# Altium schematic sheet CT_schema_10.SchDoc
size 147 x 119 mm
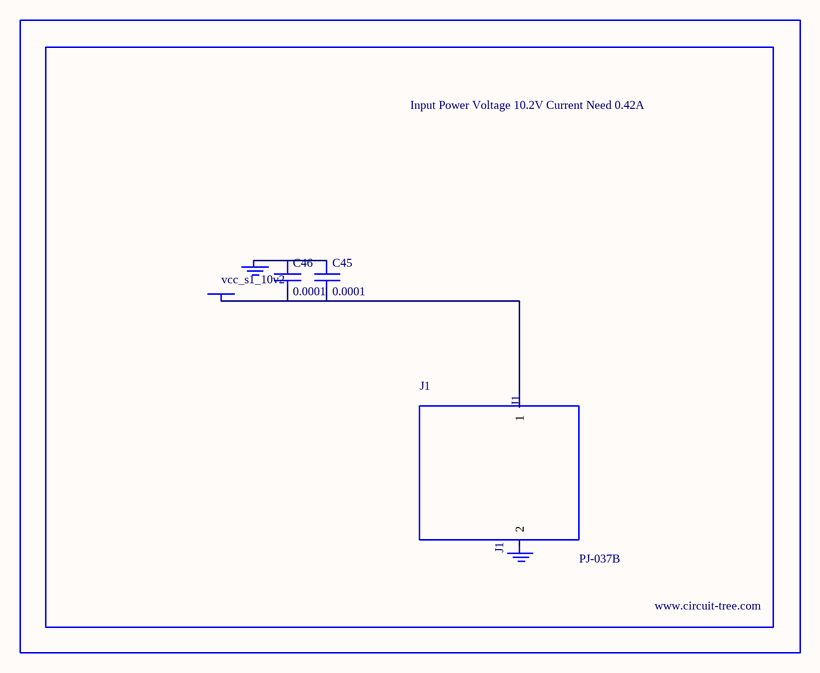
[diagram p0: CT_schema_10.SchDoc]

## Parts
BORDER9  (no value)
C45  0.0001  [EXV-9H]
C46  0.0001  [EXV-9H]
GND_INSTANCE_9_0  (no value)
GND_INSTANCE_9_1  (no value)
J1  PJ-037B  [PJ-037B_PACKAGE]
POWER_INSTANCE_9_0  vcc_s1_10v2

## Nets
NetC45_1: C45.1 C46.1 GND_INSTANCE_9_0.0(GND)
NetC45_2: C45.2 C46.2 J1.1 POWER_INSTANCE_9_0.0(PWR)

Not connected (* = marked no-connect by the designer): GND_INSTANCE_9_1 0(GND); J1 2

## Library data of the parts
BORDER9 = BORDER_PAGE9
C45 C46 = EDK107M035A9HAA
GND_INSTANCE_9_0 GND_INSTANCE_9_1 = GND
POWER_INSTANCE_9_0 = PWR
